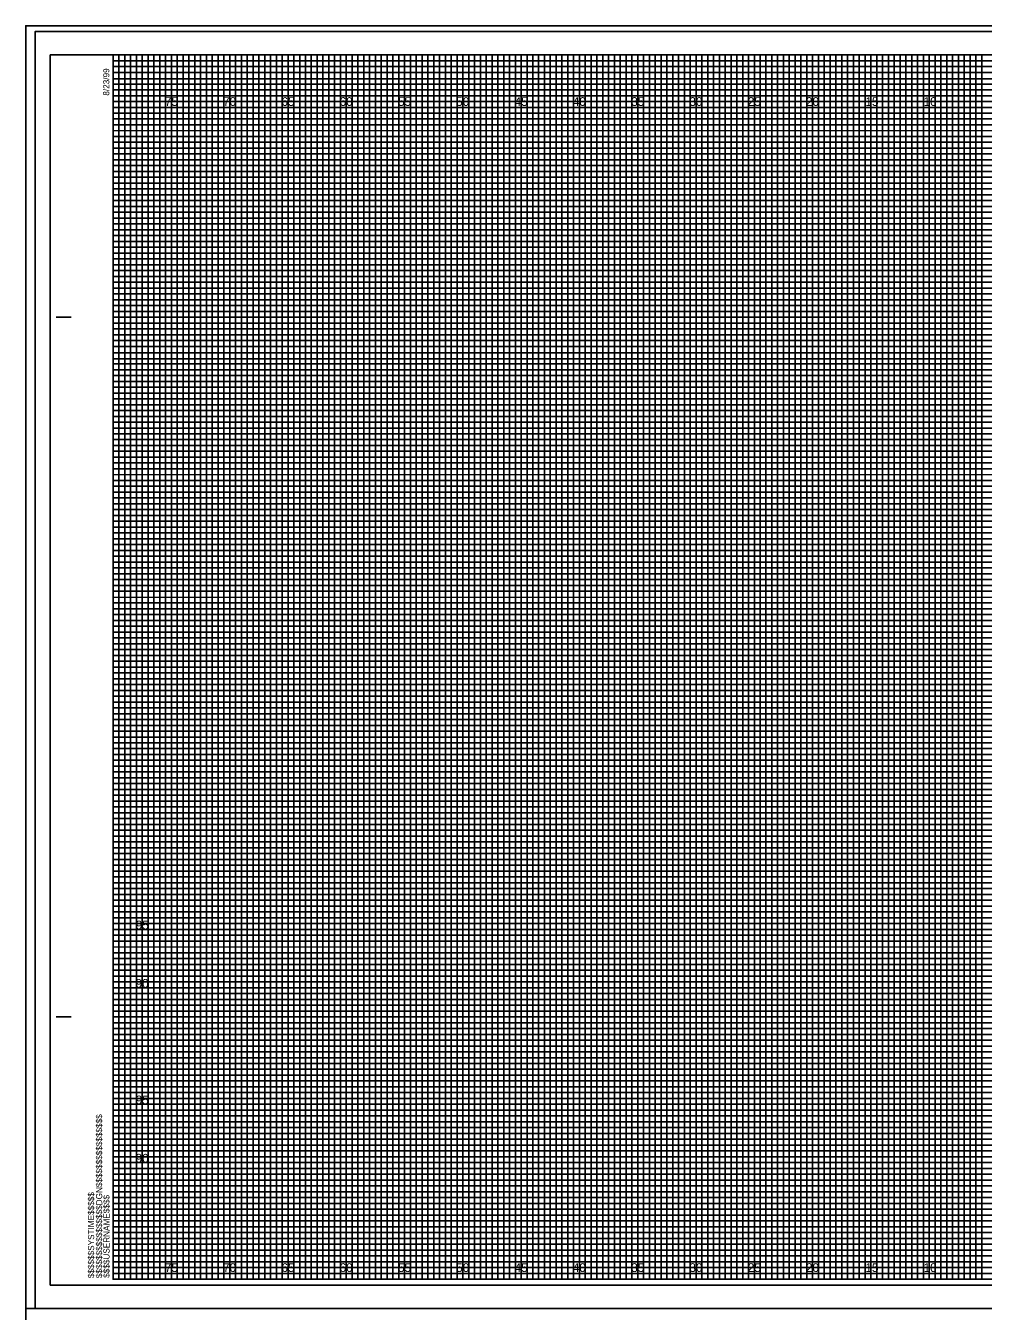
# Model space of a CAD drawing. Extents: x -8 to 533, y -20 to 768.
# Drawn here: x -7.5 to 74.6, y 657.2 to 767.5 of the extents above; entities that cross this region are included whole.
import ezdxf

# ---------------------------------------------------------------- set-up
doc = ezdxf.new("R2010")
doc.units = 0
for name, color, linetype in [('Prop XS Elevation Labels', 7, 'Continuous'), ('Prop XS Offset Labels', 7, 'Continuous'), ('Sheet Cross Section CELL', 7, 'Continuous'), ('Sheet Cross Section Grid Major CELL', 7, 'Continuous'), ('Sheet Cross Section Grid Middle CELL', 7, 'Continuous'), ('Sheet Cross Section Grid Minor 1 CELL', 7, 'Continuous'), ('Sheet Cross Section Grid Minor 2 CELL', 7, 'Continuous'), ('Sheet Cutting Line CELL', 7, 'Continuous'), ('Sheet DOT Grid CELL', 7, 'Continuous'), ('Sheet Plot Border Inside CELL', 7, 'Continuous'), ('Sheet Plot Border Outside CELL', 7, 'Continuous'), ('WEI Plot Border', 7, 'Continuous')]:
    doc.layers.add(name, color=color, linetype=linetype)

msp = doc.modelspace()

# ---------------------------------------------------------------- linework, layer by layer
at = {"layer": 'Sheet Cross Section CELL'}
for p, q in [((-4.9, 742.5), (-3.65, 742.5)), ((-4.85, 742.5), (-3.6, 742.5)), ((-4.9, 682.5), (-3.65, 682.5)), ((-4.85, 682.5), (-3.6, 682.5)), ((0, 660), (0, 660)), ((0, 660), (0, 660)), ((0, 660), (0, 660)), ((0, 660), (0, 660)), ((0, 660), (0, 660)), ((0, 660), (0, 660)), ((0, 660), (0, 660))]:
    msp.add_line(p, q, dxfattribs=at)
msp.add_lwpolyline([(160, 765), (0, 765), (0, 660), (160, 660)], close=True, dxfattribs=at)
at = {"layer": 'Sheet Cross Section Grid Major CELL'}
for p, q in [((5, 765), (0, 765)), ((5, 660), (5, 765)), ((15, 765), (10, 765)), ((10, 765), (10, 660)), ((15, 660), (15, 765)), ((25, 765), (20, 765)), ((20, 765), (20, 660)), ((25, 660), (25, 765)), ((35, 765), (30, 765)), ((30, 765), (30, 660)), ((35, 660), (35, 765)), ((45, 765), (40, 765)), ((40, 765), (40, 660)), ((45, 660), (45, 765)), ((55, 765), (50, 765)), ((50, 765), (50, 660)), ((55, 660), (55, 765)), ((65, 765), (60, 765)), ((60, 765), (60, 660)), ((65, 660), (65, 765)), ((75, 765), (70, 765)), ((70, 765), (70, 660)), ((10, 660), (5, 660)), ((20, 660), (15, 660)), ((30, 660), (25, 660)), ((40, 660), (35, 660)), ((50, 660), (45, 660)), ((60, 660), (55, 660)), ((70, 660), (65, 660))]:
    msp.add_line(p, q, dxfattribs=at)
for points in [[(0, 760), (160, 760), (160, 755), (0, 755)], [(0, 750), (160, 750), (160, 745), (0, 745)], [(0, 740), (160, 740), (160, 735), (0, 735)], [(0, 730), (160, 730), (160, 725), (0, 725)], [(0, 720), (160, 720), (160, 715), (0, 715)], [(0, 710), (160, 710), (160, 705), (0, 705)], [(0, 700), (160, 700), (160, 695), (0, 695)], [(0, 690), (160, 690), (160, 685), (0, 685)], [(0, 680), (160, 680), (160, 675), (0, 675)], [(0, 670), (160, 670), (160, 665), (0, 665)]]:
    msp.add_lwpolyline(points, dxfattribs=at)
at = {"layer": 'Sheet Cross Section Grid Middle CELL'}
for points in [[(0, 765), (2.5, 765), (2.5, 660), (7.5, 660), (7.5, 765), (12.5, 765), (12.5, 660), (17.5, 660), (17.5, 765), (22.5, 765), (22.5, 660), (27.5, 660), (27.5, 765), (32.5, 765), (32.5, 660), (37.5, 660), (37.5, 765), (42.5, 765), (42.5, 660), (47.5, 660), (47.5, 765), (52.5, 765), (52.5, 660), (57.5, 660), (57.5, 765), (62.5, 765), (62.5, 660), (67.5, 660), (67.5, 765), (72.5, 765), (72.5, 660), (77.5, 660)], [(0, 762.5), (137.5, 762.5)], [(0, 752.5), (160, 752.5), (160, 757.5), (0, 757.5)], [(0, 742.5), (160, 742.5), (160, 747.5), (0, 747.5)], [(0, 732.5), (160, 732.5), (160, 737.5), (0, 737.5)], [(0, 722.5), (160, 722.5), (160, 727.5), (0, 727.5)], [(0, 712.5), (160, 712.5), (160, 717.5), (0, 717.5)], [(0, 702.5), (160, 702.5), (160, 707.5), (0, 707.5)], [(0, 692.5), (160, 692.5), (160, 697.5), (0, 697.5)], [(0, 682.5), (160, 682.5), (160, 687.5), (0, 687.5)], [(0, 672.5), (160, 672.5), (160, 677.5), (0, 677.5)], [(0, 662.5), (160, 662.5), (160, 667.5), (0, 667.5)]]:
    msp.add_lwpolyline(points, dxfattribs=at)
at = {"layer": 'Sheet Cross Section Grid Minor 1 CELL'}
for p, q in [((0, 764.5), (130, 764.5)), ((130, 763.99), (0, 763.99)), ((0, 763.99), (0, 763.5)), ((0, 763.5), (130, 763.5)), ((130, 762.95), (0, 762.95)), ((0, 762.95), (0, 762)), ((0, 762), (160, 762))]:
    msp.add_line(p, q, dxfattribs=at)
for points in [[(0, 761.5), (135, 761.5), (160, 761.5), (160, 761), (0, 761)], [(0, 760.5), (160, 760.5), (160, 759.5), (0, 759.5)], [(0, 759), (160, 759), (160, 758.5), (0, 758.49)], [(0, 758), (160, 758), (160, 757), (0, 757)], [(0, 756.5), (160, 756.5), (160, 756), (0, 756)], [(0, 755.5), (160, 755.5), (160, 754.5), (0, 754.5)], [(0, 754), (160, 754), (160, 753.5), (0, 753.5)], [(0, 753), (160, 753), (160, 752), (0, 752)], [(0, 751.5), (160, 751.5), (160, 751), (0, 751)], [(0, 750.5), (160, 750.5), (160, 749.5), (0, 749.5)], [(0, 749), (160, 749), (160, 748.5), (0, 748.5)], [(0, 748), (160, 748), (160, 746.98), (160, 746.5), (160, 746), (0, 746)], [(0, 747), (160, 747), (160, 746.5), (0, 746.5)], [(0, 745.5), (160, 745.5), (160, 744.5), (0, 744.51)], [(0, 744.51), (160, 744.5), (160, 744), (0, 744)], [(0, 743.5), (160, 743.5), (160, 743), (0, 743)], [(0, 742), (160, 742), (160, 741.5), (0, 741.5)], [(0, 741), (160, 741), (160, 740.5), (0, 740.5)], [(-0.04, 739.45), (160, 739.45), (160, 738.94), (-0.04, 738.94)], [(0, 738.5), (160, 738.5), (160, 738), (0, 738)], [(0, 737), (160, 737), (160, 736.5), (0, 736.5)], [(0, 736), (160, 736), (160, 735.5), (0, 735.5)], [(0, 734.5), (160, 734.5), (160, 734), (0, 734)], [(0, 733.5), (160, 733.5), (160, 733), (0, 733)], [(0, 732), (160, 732), (160, 731.5), (0, 731.5)], [(0, 731), (160, 731), (160, 730.5), (0, 730.5)], [(0, 729.5), (160, 729.5), (160, 728.99), (0, 729)], [(0, 728.5), (160, 728.5), (160, 728), (0, 728)], [(0, 727), (160, 727), (160, 726.5), (0, 726.5)], [(0, 726), (160, 726), (160, 725.5), (0, 725.5)], [(0, 724.5), (160, 724.5), (160, 724), (0, 724)], [(0, 723.5), (160, 723.5), (160, 723), (0, 723)], [(0, 722), (160, 722), (160, 721.5), (0, 721.5)], [(0, 721), (160, 721), (160, 720.5), (0, 720.5)], [(0, 719.5), (160, 719.5), (160, 719), (0, 719)], [(0, 718.5), (160.03, 718.46), (160, 718), (0, 718)], [(0, 717), (160, 717), (160, 716.5), (0, 716.5)], [(0, 716), (160, 716), (160, 715.5), (0, 715.5)], [(0, 714.5), (160, 714.5), (160, 714), (0, 714)], [(0, 713.5), (160, 713.5), (160, 713), (0, 713)], [(0, 712), (160, 712), (160, 711.5), (0, 711.5)], [(0, 711), (160, 711), (160, 710.5), (0, 710.5)], [(0, 709.5), (160, 709.5), (160, 709), (0, 709)], [(0, 708.5), (160, 708.5), (160, 708), (0, 708)], [(0, 707), (160, 707), (160, 706.5), (0, 706.5)], [(0, 706), (160, 706), (160, 705.5), (0, 705.5)], [(0, 704.5), (160, 704.5), (160, 704), (0, 704)], [(0, 703.5), (160, 703.5), (160, 703), (0, 703)], [(0, 702), (160, 702), (160, 701.5), (0, 701.5)], [(0, 701), (160, 701), (160, 700.5), (0, 700.5)], [(0, 699.5), (160, 699.5), (160, 698.99), (0, 699)], [(0, 698.5), (160, 698.5), (160, 698), (0, 698)], [(0, 697), (160, 697), (160, 696.5), (0, 696.5)], [(0, 696), (160, 696), (160, 695.5), (0, 695.5)], [(0, 694.5), (160, 694.5), (160, 694), (0, 694)], [(0, 693.5), (160, 693.5), (160, 693), (0, 693)], [(0, 692), (160, 692), (160, 691.5), (0, 691.5)], [(0, 691), (160, 691), (160, 690.5), (0, 690.5)], [(0, 689.5), (160, 689.5), (160, 689), (0, 689)], [(0, 688.5), (160.03, 688.46), (160, 688), (0, 688)], [(0, 687), (160, 687), (160, 686.5), (0, 686.5)], [(0, 686), (160, 686), (160, 685.5), (0, 685.5)], [(0, 684.5), (160, 684.5), (160, 684), (0, 684)], [(0, 683.5), (160, 683.5), (160, 683), (0, 683)], [(0, 682), (160, 682), (160, 681.5), (0, 681.5)], [(0, 681), (160, 681), (160, 680.5), (0, 680.5)], [(0, 679.5), (160, 679.5), (160, 679), (0, 679)], [(0, 678.5), (160, 678.5), (160, 678), (0, 678)], [(0, 677), (160, 677), (160, 676.5), (0, 676.5)], [(0, 676), (160, 676), (160, 675.5), (0, 675.5)], [(0, 674.5), (160, 674.5), (160, 674), (0, 674)], [(0, 673.5), (160, 673.5), (160, 673), (0, 673)], [(0, 672), (160, 672), (160, 671.5), (0, 671.5)], [(0, 671), (160, 671), (160, 670.5), (0, 670.5)], [(0, 669.5), (160, 669.5), (160, 669), (0, 669)], [(0, 668.5), (160, 668.5), (160, 668), (0, 668)], [(0, 667), (160, 667), (160, 666.5), (0, 666.5)], [(0, 666), (160, 666), (160, 665.5), (0, 665.5)], [(0, 664.5), (160, 664.5), (160, 664), (0, 664)], [(0, 663.5), (160, 663.5), (160, 663), (0, 663)], [(0, 662), (160, 662), (160, 661.5), (0, 661.5)], [(0, 661), (160, 661), (160, 660.5), (0, 660.5)]]:
    msp.add_lwpolyline(points, dxfattribs=at)
at = {"layer": 'Sheet Cross Section Grid Minor 2 CELL'}
for points in [[(0, 660), (0.5, 660), (0.5, 765), (1, 765), (1, 660)], [(1, 660), (1.5, 660), (1.5, 765), (2, 765), (2, 660)], [(2.5, 660), (3, 660), (3, 765), (3.5, 765), (3.5, 660)], [(3.5, 660), (4, 660), (4, 765), (4.5, 765), (4.5, 660)], [(5, 660), (5.5, 660), (5.5, 765), (6, 765), (6, 660)], [(6, 660), (6.5, 660), (6.5, 765), (7, 765), (7, 660)], [(7.5, 660), (8, 660), (8, 765), (8.5, 765), (8.5, 660)], [(8.5, 660), (9, 660), (9, 765), (9.5, 765), (9.5, 660)], [(10, 660), (10.5, 660), (10.5, 765), (11, 765), (11, 660)], [(11, 660), (11.5, 660), (11.5, 765), (12, 765), (12, 660)], [(12.5, 660), (13, 660), (13, 765), (13.5, 765), (13.5, 660)], [(13.5, 660), (14, 660), (14, 765), (14.5, 765), (14.5, 660)], [(15, 660), (15.5, 660), (15.5, 765), (16, 765), (16, 660)], [(16, 660), (16.5, 660), (16.5, 765), (17, 765), (17, 660)], [(17.5, 660), (18, 660), (18, 765), (18.5, 765), (18.5, 660)], [(18.5, 660), (19, 660), (19, 765), (19.5, 765), (19.5, 660)], [(20, 660), (20.5, 660), (20.5, 765), (21, 765), (21, 660)], [(21, 660), (21.5, 660), (21.5, 765), (22, 765), (22, 660)], [(22.5, 660), (23, 660), (23, 765), (23.5, 765), (23.5, 660)], [(23.5, 660), (24, 660), (24, 765), (24.5, 765), (24.5, 660)], [(25, 660), (25.5, 660), (25.5, 765), (26, 765), (26, 660)], [(26, 660), (26.5, 660), (26.5, 765), (27, 765), (27, 660)], [(27.5, 660), (28, 660), (28, 765), (28.5, 765), (28.5, 660)], [(28.5, 660), (29, 660), (29, 765), (29.5, 765), (29.5, 660)], [(30, 660), (30.5, 660), (30.5, 765), (31, 765), (31, 660)], [(31, 660), (31.5, 660), (31.5, 765), (32, 765), (32, 660)], [(32.5, 660), (33, 660), (33, 765), (33.5, 765), (33.5, 660)], [(33.5, 660), (34, 660), (34, 765), (34.5, 765), (34.5, 660)], [(35, 660), (35.5, 660), (35.5, 765), (36, 765), (36, 660)], [(36, 660), (36.5, 660), (36.5, 765), (37, 765), (37, 660)], [(37.5, 660), (38, 660), (38, 765), (38.5, 765), (38.5, 660)], [(38.5, 660), (39, 660), (39, 765), (39.5, 765), (39.5, 660)], [(40, 660), (40.5, 660), (40.5, 765), (41, 765), (41, 660)], [(41, 660), (41.5, 660), (41.5, 765), (42, 765), (42, 660)], [(42.5, 660), (43, 660), (43, 765), (43.5, 765), (43.5, 660)], [(43.5, 660), (44, 660), (44, 765), (44.5, 765), (44.5, 660)], [(45, 660), (45.5, 660), (45.5, 765), (46, 765), (46, 660)], [(46, 660), (46.5, 660), (46.5, 765), (47, 765), (47, 660)], [(47.5, 660), (48, 660), (48, 765), (48.5, 765), (48.5, 660)], [(48.5, 660), (49, 660), (49, 765), (49.5, 765), (49.5, 660)], [(50, 660), (50.5, 660), (50.5, 765), (51, 765), (51, 660)], [(51, 660), (51.5, 660), (51.5, 765), (52, 765), (52, 660)], [(52.5, 660), (53, 660), (53, 765), (53.5, 765), (53.5, 660)], [(53.5, 660), (54, 660), (54, 765), (54.5, 765), (54.5, 660)], [(55, 660), (55.5, 660), (55.5, 765), (56, 765), (56, 660)], [(56, 660), (56.5, 660), (56.5, 765), (57, 765), (57, 660)], [(57.5, 660), (58, 660), (58, 765), (58.5, 765), (58.5, 660)], [(58.5, 660), (59, 660), (59, 765), (59.5, 765), (59.5, 660)], [(60, 660), (60.5, 660), (60.5, 765), (61, 765), (61, 660)], [(61, 660), (61.5, 660), (61.5, 765), (62, 765), (62, 660)], [(62.5, 660), (63, 660), (63, 765), (63.5, 765), (63.5, 660)], [(63.5, 660), (64, 660), (64, 765), (64.5, 765), (64.5, 660)], [(65, 660), (65.5, 660), (65.5, 765), (66, 765), (66, 660)], [(66, 660), (66.5, 660), (66.5, 765), (67, 765), (67, 660)], [(67.5, 660), (68, 660), (68, 765), (68.5, 765), (68.5, 660)], [(68.5, 660), (69, 660), (69, 765), (69.5, 765), (69.5, 660)], [(70, 660), (70.5, 660), (70.5, 765), (71, 765), (71, 660)], [(71, 660), (71.5, 660), (71.5, 765), (72, 765), (72, 660)], [(72.5, 660), (73, 660), (73, 765), (73.5, 765), (73.5, 660)], [(73.5, 660), (74, 660), (74, 765), (74.5, 765), (74.5, 660)]]:
    msp.add_lwpolyline(points, dxfattribs=at)
at = {"layer": 'Sheet Cutting Line CELL'}
for p, q in [((161.65, 767), (-6.7, 767)), ((-6.7, 767), (-6.7, 657.5)), ((-6.7, 657.5), (161.65, 657.5))]:
    msp.add_line(p, q, dxfattribs=at)
at = {"layer": 'Sheet DOT Grid CELL'}
for p, q in [((5, 660), (5, 765)), ((10, 660), (10, 765)), ((15, 660), (15, 765)), ((20, 660), (20, 765)), ((25, 660), (25, 765)), ((30, 660), (30, 765)), ((35, 660), (35, 765)), ((40, 660), (40, 765)), ((45, 660), (45, 765)), ((50, 660), (50, 765)), ((55, 660), (55, 765)), ((60, 660), (60, 765)), ((65, 660), (65, 765)), ((70, 660), (70, 765)), ((0, 760), (160, 760)), ((0, 755), (160, 755)), ((0, 750), (160, 750)), ((0, 745), (160, 745)), ((0, 740), (160, 740)), ((0, 735), (160, 735)), ((0, 730), (160, 730)), ((0, 725), (160, 725)), ((0, 720), (160, 720)), ((0, 715), (160, 715)), ((0, 710), (160, 710)), ((0, 705), (160, 705)), ((0, 700), (160, 700)), ((0, 695), (160, 695)), ((0, 690), (160, 690)), ((0, 685), (160, 685)), ((0, 680), (160, 680)), ((0, 675), (160, 675)), ((0, 670), (160, 670)), ((0, 665), (160, 665))]:
    msp.add_line(p, q, dxfattribs=at)
at = {"layer": 'Sheet Plot Border Inside CELL'}
msp.add_lwpolyline([(-5.4, 659.5), (161.2, 659.5), (161.2, 765), (-5.4, 765)], close=True, dxfattribs=at)
at = {"layer": 'Sheet Plot Border Outside CELL'}
msp.add_lwpolyline([(-6.7, 657.5), (161.65, 657.5), (161.65, 767), (-6.7, 767)], close=True, dxfattribs=at)
at = {"layer": 'WEI Plot Border'}
for points in [[(-7.5, 657.5), (162.5, 657.5), (162.5, 767.5), (-7.5, 767.5)], [(-7.5, 547.5), (162.5, 547.5), (162.5, 657.5), (-7.5, 657.5)]]:
    msp.add_lwpolyline(points, close=True, dxfattribs=at)

# ---------------------------------------------------------------- texts
at = {"layer": 'Prop XS Elevation Labels'}
for s, p in [('95', (1.94, 690)), ('90', (1.93, 685)), ('95', (1.94, 675)), ('90', (1.93, 670))]:
    msp.add_text(s, height=0.75, dxfattribs=at).set_placement(p)
at = {"layer": 'Prop XS Offset Labels'}
for s, p in [('75', (4.44, 760.62)), ('70', (9.43, 760.62)), ('65', (14.44, 760.62)), ('60', (19.43, 760.62)), ('55', (24.44, 760.62)), ('50', (29.43, 760.62)), ('45', (34.44, 760.62)), ('40', (39.43, 760.62)), ('35', (44.44, 760.62)), ('30', (49.43, 760.62)), ('25', (54.44, 760.62)), ('20', (59.43, 760.62)), ('15', (64.53, 760.62)), ('10', (69.52, 760.62)), ('75', (4.44, 660.62)), ('70', (9.43, 660.62)), ('65', (14.44, 660.62)), ('60', (19.43, 660.62)), ('55', (24.44, 660.62)), ('50', (29.43, 660.62)), ('45', (34.44, 660.62)), ('40', (39.43, 660.62)), ('35', (44.44, 660.62)), ('30', (49.43, 660.62)), ('25', (54.44, 660.62)), ('20', (59.43, 660.62)), ('15', (64.53, 660.62)), ('10', (69.52, 660.62))]:
    msp.add_text(s, height=0.75, dxfattribs=at).set_placement(p)
at = {"layer": 'Sheet Cross Section CELL'}
for s, p in [('8/23/99', (-0.33, 761.5)), ('$$$$$$$$$$$$$$$$DGN$$$$$$$$$$$$$$$$', (-0.94, 660.09)), ('$$$$$$SYSTIME$$$$$', (-1.63, 660.09)), ('$$$$USERNAME$$$$', (-0.31, 660.12))]:
    msp.add_text(s, height=0.525, rotation=90, dxfattribs=at).set_placement(p)

doc.saveas('drawing.dxf')
